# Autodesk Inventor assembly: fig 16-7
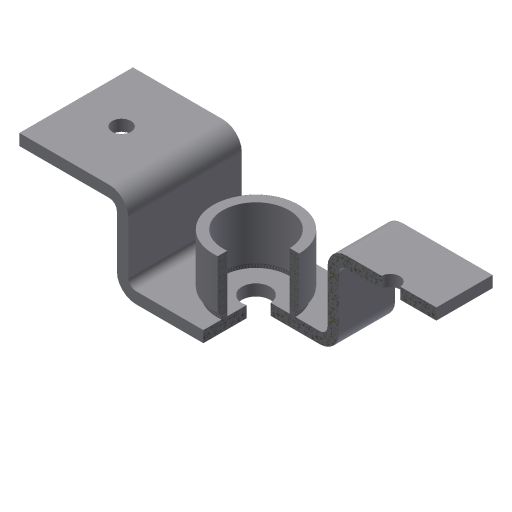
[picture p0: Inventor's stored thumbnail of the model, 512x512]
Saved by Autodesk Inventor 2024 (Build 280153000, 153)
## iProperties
Created: 2005-03
Part Number: fig 16-7
Document SubType Name: Weldment
Designer: CADCIM
Manufacturer: Standard
Standards Organization: Custom
Author: CADCIM
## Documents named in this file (3)
- D:\PROJECTS\Project 2023\RESOURCES INVENTOR 2024\RESOURCES INVENTOR 2024\Inventor_2023_Part\Inventor_2024_Part\c16_Inv_2024_prt\fig 16-7\fig 16-7.iam
- D:\PROJECTS\Project 2023\RESOURCES INVENTOR 2024\RESOURCES INVENTOR 2024\Inventor_2023_Part\Inventor_2024_Part\c16_Inv_2024_prt\fig 16-7\Bracket.ipt
- D:\PROJECTS\Project 2023\RESOURCES INVENTOR 2024\RESOURCES INVENTOR 2024\Inventor_2023_Part\Inventor_2024_Part\c16_Inv_2024_prt\fig 16-7\cylinder.ipt
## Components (2 placed, 2 different names)
1. Bracket:1 — Insert:1
2. cylinder:1 — Insert:1
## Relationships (1: Insert 1)
- Insert:1: Bracket:1 ↔ cylinder:1
